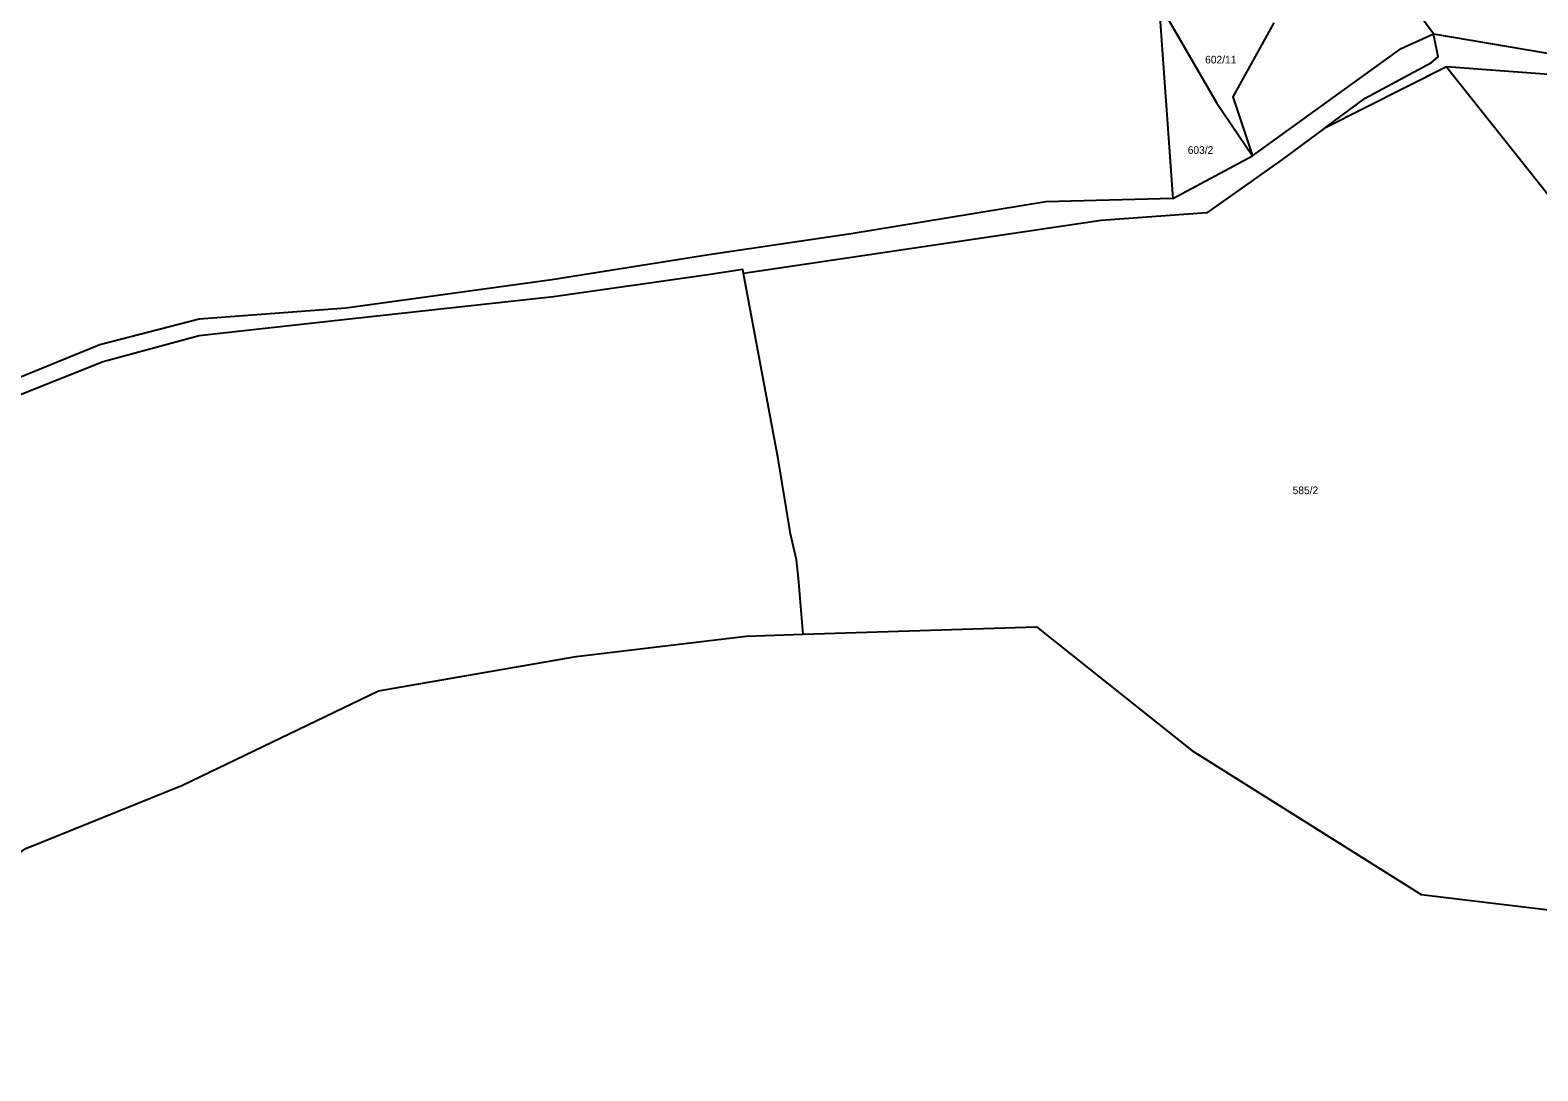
# Model space of a CAD drawing. Extents: x -887272 to -880188, y -1026687 to -1021896.
# Drawn here: x -884435.6 to -884099.9, y -1024259.7 to -1024028 of the extents above; entities that cross this region are included whole.
import ezdxf

# ---------------------------------------------------------------- set-up
doc = ezdxf.new("R2010")
doc.units = 0
doc.layers.add('Hranice parcel', color=7, linetype='Continuous')
doc.layers.add('Parcelní čísla', color=7, linetype='Continuous')

msp = doc.modelspace()

# ---------------------------------------------------------------- linework, layer by layer
at = {"layer": 'Hranice parcel'}
for p, q in [((-884184.24, -1024021.97), (-884181.13, -1024065.5)), ((-884120.19, -1024036.18), (-884147.43, -1024049.88)), ((-884120.19, -1024036.18), (-884023.67, -1024157.61)), ((-884181.13, -1024065.5), (-884163.4, -1024055.98))]:
    msp.add_line(p, q, dxfattribs=at)
for points in [[(-884123.06, -1024028.78), (-884154.74, -1023986.16), (-884183.74, -1023946.37), (-884186.39, -1023943.42), (-884212.89, -1023917.78), (-884216.25, -1023915.48), (-884266.73, -1023886.51), (-884264.84, -1023879.03)], [(-884184.24, -1024021.97), (-884171.36, -1024044.23), (-884163.4, -1024055.98)], [(-884158.67, -1024026.32), (-884167.73, -1024042.82), (-884163.4, -1024055.98)], [(-884163.4, -1024055.98), (-884130.26, -1024032.06), (-884123.06, -1024028.78)], [(-884147.43, -1024049.88), (-884138.31, -1024043.15), (-884123.51, -1024035.22), (-884122.06, -1024033.92), (-884123.06, -1024028.78)], [(-884123.06, -1024028.78), (-884098.18, -1024033), (-884045.1, -1024039.86), (-884004.26, -1024040.76), (-883995.38, -1024045.56)], [(-883918.72, -1024101.7), (-883924.14, -1024097.32), (-883952.02, -1024075.4), (-883984.02, -1024054.24), (-883999.74, -1024046.96), (-884016.72, -1024045.28), (-884043.42, -1024044.88), (-884080.84, -1024039.76), (-884098.38, -1024037.82), (-884120.19, -1024036.18)], [(-884147.43, -1024049.88), (-884157.06, -1024057.03), (-884173.59, -1024068.65), (-884197.06, -1024070.35), (-884276.73, -1024082.15)], [(-884181.13, -1024065.5), (-884209.4, -1024066.2), (-884252.74, -1024073.36), (-884284.46, -1024078.02), (-884319.41, -1024083.55), (-884365.28, -1024089.9), (-884397.9, -1024092.38), (-884420.08, -1024098.04), (-884440.24, -1024106.32), (-884466.24, -1024120.5), (-884487.94, -1024133.38), (-884521.62, -1024152.96), (-884545.9, -1024165.96), (-884580.96, -1024184.66), (-884593.64, -1024193.4), (-884611.34, -1024216.98), (-884624.48, -1024229.34)], [(-884276.73, -1024082.15), (-884276.89, -1024081.31), (-884284.12, -1024082.38), (-884319.02, -1024087.38), (-884365.82, -1024092.5), (-884397.92, -1024096.08), (-884419.32, -1024101.84), (-884438.66, -1024109.56), (-884464.4, -1024123.78), (-884489.46, -1024138.46), (-884519.96, -1024156.1), (-884547.76, -1024170.96), (-884561.96, -1024178.42), (-884579.92, -1024188.16), (-884591.08, -1024195.74), (-884607.66, -1024217.98), (-884624.46, -1024233.86), (-884651.92, -1024248.06), (-884671.24, -1024252.12), (-884684.88, -1024249.66), (-884699.4, -1024243.82), (-884720.9, -1024231.66)], [(-884263.42, -1024162.52), (-884264.45, -1024150.02), (-884264.94, -1024145.97), (-884266.23, -1024140.17), (-884269.01, -1024123.46), (-884276.73, -1024082.15)], [(-884263.42, -1024162.52), (-884211.46, -1024160.89), (-884176.88, -1024188.36), (-884125.84, -1024220.46), (-884090.08, -1024224.8), (-884078.6, -1024224)], [(-884632.54, -1024600.92), (-884611.4, -1024534.54), (-884600.3, -1024477.36), (-884616.3, -1024447.82), (-884582.76, -1024432.52), (-884565.62, -1024395.46), (-884557.28, -1024343.32), (-884547.24, -1024324.6), (-884531.28, -1024294.22), (-884498.6, -1024253.22), (-884436.5, -1024210.2), (-884401.62, -1024196.08), (-884358, -1024175.14), (-884313.98, -1024167.46), (-884276.16, -1024162.92), (-884263.42, -1024162.52)]]:
    msp.add_lwpolyline(points, dxfattribs=at)

# ---------------------------------------------------------------- texts
at = {"layer": 'Parcelní čísla'}
for s, p in [('602/11', (-884173.93, -1024035.4)), ('603/2', (-884177.81, -1024055.53)), ('585/2', (-884154.45, -1024131.31))]:
    msp.add_text(s, height=1.7, dxfattribs=at).set_placement(p)

doc.saveas('drawing.dxf')
